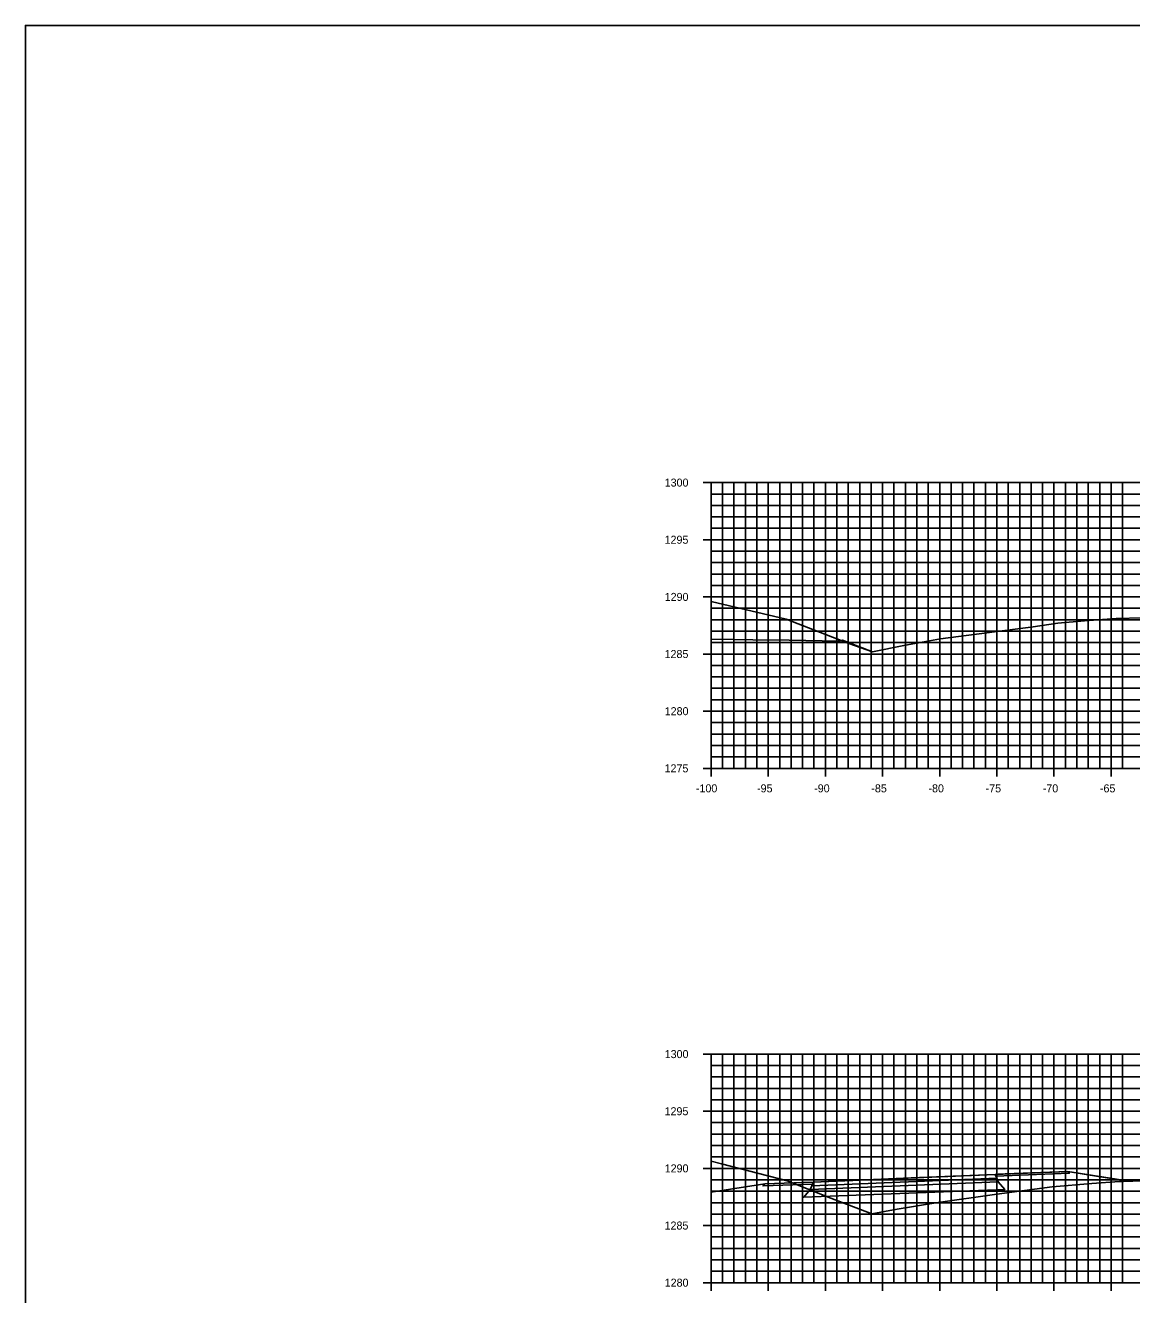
# Model space of a CAD drawing. Extents: x 674939 to 678919, y 750652 to 765176.
# Drawn here: x 677778.5 to 677875.3, y 758391.5 to 758502.6 of the extents above; entities that cross this region are included whole.
import ezdxf

# ---------------------------------------------------------------- set-up
doc = ezdxf.new("R2010")
doc.units = 0
for name, color, linetype in [('R_Alt Surface', 7, 'Continuous'), ('R_Axis', 7, 'Continuous'), ('R_Axis Annot', 7, 'Continuous'), ('R_Exist Surface', 7, 'Continuous'), ('R_Fin Surface', 7, 'Continuous'), ('R_Grid', 7, 'Continuous'), ('R_No Plot', 7, 'Continuous'), ('R_Proposed Road', 7, 'Continuous')]:
    doc.layers.add(name, color=color, linetype=linetype)

msp = doc.modelspace()

# ---------------------------------------------------------------- linework, layer by layer
at = {"layer": 'R_Alt Surface'}
for points in [[(677863.52, 758401.69), (677847.34, 758401.02), (677847.21, 758400.69), (677863.65, 758401.36)], [(677863.65, 758401.36), (677847.21, 758400.69), (677846.63, 758400.02), (677864.23, 758400.7)]]:
    msp.add_lwpolyline(points, close=True, dxfattribs=at)
at = {"layer": 'R_Axis'}
for p, q in [((677837.83, 758462.55), (677839.23, 758462.55)), ((677838.53, 758437.55), (677838.53, 758462.55)), ((677838.53, 758461.55), (677838.88, 758461.55)), ((677838.53, 758460.55), (677838.88, 758460.55)), ((677838.53, 758459.55), (677838.88, 758459.55)), ((677838.53, 758458.55), (677838.88, 758458.55)), ((677837.83, 758457.55), (677839.23, 758457.55)), ((677838.53, 758456.55), (677838.88, 758456.55)), ((677838.53, 758455.55), (677838.88, 758455.55)), ((677838.53, 758454.55), (677838.88, 758454.55)), ((677837.83, 758452.55), (677839.23, 758452.55)), ((677838.53, 758453.55), (677838.88, 758453.55)), ((677838.53, 758451.55), (677838.88, 758451.55)), ((677838.53, 758450.55), (677838.88, 758450.55)), ((677838.53, 758449.55), (677838.88, 758449.55)), ((677838.53, 758448.55), (677838.88, 758448.55)), ((677837.83, 758447.55), (677839.23, 758447.55)), ((677838.53, 758446.55), (677838.88, 758446.55)), ((677838.53, 758445.55), (677838.88, 758445.55)), ((677838.53, 758444.55), (677838.88, 758444.55)), ((677837.83, 758442.55), (677839.23, 758442.55)), ((677838.53, 758443.55), (677838.88, 758443.55)), ((677838.53, 758441.55), (677838.88, 758441.55)), ((677838.53, 758440.55), (677838.88, 758440.55)), ((677838.53, 758439.55), (677838.88, 758439.55)), ((677838.53, 758438.55), (677838.88, 758438.55)), ((677838.53, 758436.85), (677838.53, 758438.25)), ((677843.53, 758436.85), (677843.53, 758438.25)), ((677848.53, 758436.85), (677848.53, 758438.25)), ((677853.53, 758436.85), (677853.53, 758438.25)), ((677858.53, 758436.85), (677858.53, 758438.25)), ((677863.53, 758436.85), (677863.53, 758438.25)), ((677868.53, 758436.85), (677868.53, 758438.25)), ((677873.53, 758436.85), (677873.53, 758438.25)), ((677837.83, 758437.55), (677839.23, 758437.55)), ((677838.53, 758437.55), (678038.53, 758437.55)), ((677837.83, 758412.55), (677839.23, 758412.55)), ((677838.53, 758392.55), (677838.53, 758412.55)), ((677838.53, 758411.55), (677838.88, 758411.55)), ((677838.53, 758410.55), (677838.88, 758410.55)), ((677838.53, 758409.55), (677838.88, 758409.55)), ((677838.53, 758408.55), (677838.88, 758408.55)), ((677837.83, 758407.55), (677839.23, 758407.55)), ((677838.53, 758406.55), (677838.88, 758406.55)), ((677838.53, 758405.55), (677838.88, 758405.55)), ((677838.53, 758404.55), (677838.88, 758404.55)), ((677838.53, 758403.55), (677838.88, 758403.55)), ((677837.83, 758402.55), (677839.23, 758402.55)), ((677838.53, 758401.55), (677838.88, 758401.55)), ((677838.53, 758400.55), (677838.88, 758400.55)), ((677838.53, 758399.55), (677838.88, 758399.55)), ((677838.53, 758398.55), (677838.88, 758398.55)), ((677837.83, 758397.55), (677839.23, 758397.55)), ((677838.53, 758396.55), (677838.88, 758396.55)), ((677838.53, 758395.55), (677838.88, 758395.55)), ((677838.53, 758394.55), (677838.88, 758394.55)), ((677838.53, 758393.55), (677838.88, 758393.55)), ((677838.53, 758391.85), (677838.53, 758393.25)), ((677843.53, 758391.85), (677843.53, 758393.25)), ((677848.53, 758391.85), (677848.53, 758393.25)), ((677853.53, 758391.85), (677853.53, 758393.25)), ((677858.53, 758391.85), (677858.53, 758393.25)), ((677863.53, 758391.85), (677863.53, 758393.25)), ((677868.53, 758391.85), (677868.53, 758393.25)), ((677873.53, 758391.85), (677873.53, 758393.25)), ((677837.83, 758392.55), (677839.23, 758392.55)), ((677838.53, 758392.55), (678038.53, 758392.55))]:
    msp.add_line(p, q, dxfattribs=at)
at = {"layer": 'R_Exist Surface'}
for points in [[(677838.53, 758452.14), (677845.09, 758450.6), (677850.57, 758448.48), (677852.64, 758447.74), (677855.38, 758448.29), (677858.6, 758448.88), (677866.72, 758449.94), (677868.87, 758450.25), (677871.19, 758450.46), (677873.97, 758450.67), (677873.98, 758450.67), (677876.27, 758450.71)], [(677838.53, 758403.17), (677839.43, 758402.94), (677845.2, 758401.47), (677849.02, 758399.93), (677852.58, 758398.57), (677854.82, 758398.98), (677858.19, 758399.53), (677863.52, 758400.28), (677868.38, 758400.94), (677871.84, 758401.22), (677874.26, 758401.4), (677874.61, 758401.41), (677877.03, 758401.49)]]:
    msp.add_lwpolyline(points, dxfattribs=at)
at = {"layer": 'R_Fin Surface'}
msp.add_lwpolyline([(677847.47, 758401.34), (677847.34, 758401.02), (677863.52, 758401.69), (677863.39, 758402.02)], close=True, dxfattribs=at)
msp.add_lwpolyline([(677869.73, 758402.29), (677875.11, 758401.43)], dxfattribs=at)
at = {"layer": 'R_Grid'}
for p, q in [((677838.53, 758462.55), (678038.53, 758462.55)), ((677838.53, 758437.55), (677838.53, 758462.55)), ((677839.53, 758437.55), (677839.53, 758462.55)), ((677840.53, 758437.55), (677840.53, 758462.55)), ((677841.53, 758437.55), (677841.53, 758462.55)), ((677842.53, 758437.55), (677842.53, 758462.55)), ((677843.53, 758437.55), (677843.53, 758462.55)), ((677844.53, 758437.55), (677844.53, 758462.55)), ((677845.53, 758437.55), (677845.53, 758462.55)), ((677846.53, 758437.55), (677846.53, 758462.55)), ((677847.53, 758437.55), (677847.53, 758462.55)), ((677848.53, 758437.55), (677848.53, 758462.55)), ((677849.53, 758437.55), (677849.53, 758462.55)), ((677850.53, 758437.55), (677850.53, 758462.55)), ((677851.53, 758437.55), (677851.53, 758462.55)), ((677852.53, 758437.55), (677852.53, 758462.55)), ((677853.53, 758437.55), (677853.53, 758462.55)), ((677854.53, 758437.55), (677854.53, 758462.55)), ((677855.53, 758437.55), (677855.53, 758462.55)), ((677856.53, 758437.55), (677856.53, 758462.55)), ((677857.53, 758437.55), (677857.53, 758462.55)), ((677858.53, 758437.55), (677858.53, 758462.55)), ((677859.53, 758437.55), (677859.53, 758462.55)), ((677860.53, 758437.55), (677860.53, 758462.55)), ((677861.53, 758437.55), (677861.53, 758462.55)), ((677862.53, 758437.55), (677862.53, 758462.55)), ((677863.53, 758437.55), (677863.53, 758462.55)), ((677864.53, 758437.55), (677864.53, 758462.55)), ((677865.53, 758437.55), (677865.53, 758462.55)), ((677866.53, 758437.55), (677866.53, 758462.55)), ((677867.53, 758437.55), (677867.53, 758462.55)), ((677868.53, 758437.55), (677868.53, 758462.55)), ((677869.53, 758437.55), (677869.53, 758462.55)), ((677870.53, 758437.55), (677870.53, 758462.55)), ((677871.53, 758437.55), (677871.53, 758462.55)), ((677872.53, 758437.55), (677872.53, 758462.55)), ((677873.53, 758437.55), (677873.53, 758462.55)), ((677874.53, 758437.55), (677874.53, 758462.55)), ((677838.53, 758461.55), (678038.53, 758461.55)), ((677838.53, 758460.55), (678038.53, 758460.55)), ((677838.53, 758459.55), (678038.53, 758459.55)), ((677838.53, 758458.55), (678038.53, 758458.55)), ((677838.53, 758457.55), (678038.53, 758457.55)), ((677838.53, 758456.55), (678038.53, 758456.55)), ((677838.53, 758455.55), (678038.53, 758455.55)), ((677838.53, 758454.55), (678038.53, 758454.55)), ((677838.53, 758453.55), (678038.53, 758453.55)), ((677838.53, 758452.55), (678038.53, 758452.55)), ((677838.53, 758451.55), (678038.53, 758451.55)), ((677838.53, 758450.55), (678038.53, 758450.55)), ((677838.53, 758449.55), (678038.53, 758449.55)), ((677838.53, 758448.55), (678038.53, 758448.55)), ((677838.53, 758447.55), (678038.53, 758447.55)), ((677838.53, 758446.55), (678038.53, 758446.55)), ((677838.53, 758445.55), (678038.53, 758445.55)), ((677838.53, 758444.55), (678038.53, 758444.55)), ((677838.53, 758443.55), (678038.53, 758443.55)), ((677838.53, 758442.55), (678038.53, 758442.55)), ((677838.53, 758441.55), (678038.53, 758441.55)), ((677838.53, 758440.55), (678038.53, 758440.55)), ((677838.53, 758439.55), (678038.53, 758439.55)), ((677838.53, 758438.55), (678038.53, 758438.55)), ((677838.53, 758437.55), (678038.53, 758437.55)), ((677838.53, 758412.55), (678038.53, 758412.55)), ((677838.53, 758392.55), (677838.53, 758412.55)), ((677838.53, 758411.55), (678038.53, 758411.55)), ((677839.53, 758392.55), (677839.53, 758412.55)), ((677840.53, 758392.55), (677840.53, 758412.55)), ((677841.53, 758392.55), (677841.53, 758412.55)), ((677842.53, 758392.55), (677842.53, 758412.55)), ((677843.53, 758392.55), (677843.53, 758412.55)), ((677844.53, 758392.55), (677844.53, 758412.55)), ((677845.53, 758392.55), (677845.53, 758412.55)), ((677846.53, 758392.55), (677846.53, 758412.55)), ((677847.53, 758392.55), (677847.53, 758412.55)), ((677848.53, 758392.55), (677848.53, 758412.55)), ((677849.53, 758392.55), (677849.53, 758412.55)), ((677850.53, 758392.55), (677850.53, 758412.55)), ((677851.53, 758392.55), (677851.53, 758412.55)), ((677852.53, 758392.55), (677852.53, 758412.55)), ((677853.53, 758392.55), (677853.53, 758412.55)), ((677854.53, 758392.55), (677854.53, 758412.55)), ((677855.53, 758392.55), (677855.53, 758412.55)), ((677856.53, 758392.55), (677856.53, 758412.55)), ((677857.53, 758392.55), (677857.53, 758412.55)), ((677858.53, 758392.55), (677858.53, 758412.55)), ((677859.53, 758392.55), (677859.53, 758412.55)), ((677860.53, 758392.55), (677860.53, 758412.55)), ((677861.53, 758392.55), (677861.53, 758412.55)), ((677862.53, 758392.55), (677862.53, 758412.55)), ((677863.53, 758392.55), (677863.53, 758412.55)), ((677864.53, 758392.55), (677864.53, 758412.55)), ((677865.53, 758392.55), (677865.53, 758412.55)), ((677866.53, 758392.55), (677866.53, 758412.55)), ((677867.53, 758392.55), (677867.53, 758412.55)), ((677868.53, 758392.55), (677868.53, 758412.55)), ((677869.53, 758392.55), (677869.53, 758412.55)), ((677870.53, 758392.55), (677870.53, 758412.55)), ((677871.53, 758392.55), (677871.53, 758412.55)), ((677872.53, 758392.55), (677872.53, 758412.55)), ((677873.53, 758392.55), (677873.53, 758412.55)), ((677874.53, 758392.55), (677874.53, 758412.55)), ((677838.53, 758410.55), (678038.53, 758410.55)), ((677838.53, 758409.55), (678038.53, 758409.55)), ((677838.53, 758408.55), (678038.53, 758408.55)), ((677838.53, 758407.55), (678038.53, 758407.55)), ((677838.53, 758406.55), (678038.53, 758406.55)), ((677838.53, 758405.55), (678038.53, 758405.55)), ((677838.53, 758404.55), (678038.53, 758404.55)), ((677838.53, 758403.55), (678038.53, 758403.55)), ((677838.53, 758402.55), (678038.53, 758402.55)), ((677838.53, 758401.55), (678038.53, 758401.55)), ((677838.53, 758400.55), (678038.53, 758400.55)), ((677838.53, 758399.55), (678038.53, 758399.55)), ((677838.53, 758398.55), (678038.53, 758398.55)), ((677838.53, 758397.55), (678038.53, 758397.55)), ((677838.53, 758396.55), (678038.53, 758396.55)), ((677838.53, 758395.55), (678038.53, 758395.55)), ((677838.53, 758394.55), (678038.53, 758394.55)), ((677838.53, 758393.55), (678038.53, 758393.55)), ((677838.53, 758392.55), (678038.53, 758392.55))]:
    msp.add_line(p, q, dxfattribs=at)
at = {"layer": 'R_No Plot'}
msp.add_lwpolyline([(677778.53, 758282.55), (678118.53, 758282.55), (678118.53, 758502.55), (677778.53, 758502.55)], close=True, dxfattribs=at)
for points in [[(677838.53, 758448.86), (677840.5, 758448.83), (677842.17, 758448.8), (677845.36, 758448.75), (677849.71, 758448.69), (677850.02, 758448.76), (677850.85, 758448.44), (677852.64, 758447.74)], [(677838.53, 758400.46), (677843.22, 758401.19), (677846.62, 758401.31), (677847.47, 758401.34), (677849.44, 758401.43), (677856.04, 758401.72), (677863.39, 758402.02), (677863.64, 758402.04), (677864.26, 758402.06), (677869.73, 758402.29), (677872.44, 758401.85), (677875.11, 758401.43)]]:
    msp.add_lwpolyline(points, dxfattribs=at)
at = {"layer": 'R_Proposed Road'}
for points in [[(677863.39, 758402.02), (677869.73, 758402.29), (677869.86, 758402.12), (677863.45, 758401.86)], [(677847.47, 758401.34), (677843.22, 758401.19), (677843.08, 758401.02), (677847.41, 758401.18)]]:
    msp.add_lwpolyline(points, close=True, dxfattribs=at)

# ---------------------------------------------------------------- texts
at = {"layer": 'R_Axis Annot'}
for s, p in [('1300', (677834.47, 758462.2)), ('1295', (677834.46, 758457.2)), ('1290', (677834.47, 758452.2)), ('1285', (677834.46, 758447.2)), ('1280', (677834.47, 758442.2)), ('1275', (677834.46, 758437.2)), ('-100', (677837.2, 758435.45)), ('-95', (677842.55, 758435.45)), ('-90', (677847.55, 758435.45)), ('-85', (677852.55, 758435.45)), ('-80', (677857.55, 758435.45)), ('-75', (677862.55, 758435.45)), ('-70', (677867.55, 758435.45)), ('-65', (677872.55, 758435.45)), ('1300', (677834.47, 758412.2)), ('1295', (677834.46, 758407.2)), ('1290', (677834.47, 758402.2)), ('1285', (677834.46, 758397.2)), ('1280', (677834.47, 758392.2))]:
    msp.add_text(s, height=0.7, dxfattribs=at).set_placement(p)

doc.saveas('drawing.dxf')
